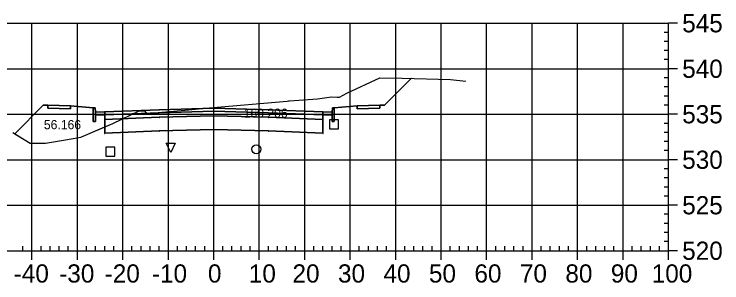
# Model space of a CAD drawing. Extents: x 704834 to 709892, y 372981 to 377533.
# Drawn here: x 705543 to 705698.6, y 373825.8 to 373884.8 of the extents above; entities that cross this region are included whole.
import ezdxf

# ---------------------------------------------------------------- set-up
doc = ezdxf.new("R2010")
doc.units = 0
for name, color, linetype in [('1', 7, 'Continuous'), ('10', 7, 'Continuous'), ('13', 7, 'Continuous'), ('14', 7, 'Continuous'), ('4', 7, 'Continuous'), ('57', 7, 'Continuous'), ('59', 7, 'Continuous'), ('Default_Xsect', 7, 'Continuous'), ('Existing', 7, 'Continuous')]:
    doc.layers.add(name, color=color, linetype=linetype)

msp = doc.modelspace()

# ---------------------------------------------------------------- linework, layer by layer
for points in [[(705624.37, 373864.81), (705630.25, 373870.68)], [(705549.37, 373864.81), (705543.1, 373858.54)], [(705550.37, 373864.85), (705549.37, 373864.81)], [(705560.37, 373864.25), (705555.37, 373864.65)], [(705613.37, 373864.25), (705618.37, 373864.65)], [(705623.37, 373864.85), (705624.37, 373864.81)]]:
    msp.add_lwpolyline(points)
for points in [[(705555.37, 373864.65), (705550.37, 373864.85), (705550.37, 373864.18), (705555.37, 373863.98)], [(705560.87, 373863.25), (705560.79, 373864.25), (705560.37, 373864.25), (705560.37, 373861.25), (705560.87, 373861.25)], [(705586.87, 373863.5), (705598.87, 373863.14), (705610.87, 373862.66), (705610.87, 373863.33), (705598.87, 373863.81), (705586.87, 373864.17), (705574.87, 373863.81), (705562.87, 373863.33), (705562.87, 373862.66), (705574.87, 373863.14)], [(705586.87, 373862.5), (705598.87, 373862.14), (705610.87, 373861.66), (705610.87, 373862.66), (705598.87, 373863.14), (705586.87, 373863.5), (705574.87, 373863.14), (705562.87, 373862.66), (705562.87, 373861.66), (705574.87, 373862.14)], [(705586.82, 373863.45), (705586.92, 373863.45), (705586.92, 373863.55), (705586.82, 373863.55)], [(705612.87, 373861.25), (705613.37, 373861.25), (705613.37, 373864.25), (705612.96, 373864.25), (705612.87, 373863.25)], [(705618.37, 373863.98), (705623.37, 373864.18), (705623.37, 373864.85), (705618.37, 373864.65)], [(705562.87, 373863.33), (705560.87, 373863.25), (705560.87, 373862.58), (705562.87, 373862.66)], [(705586.87, 373859.5), (705598.87, 373859.14), (705610.87, 373858.66), (705610.87, 373861.66), (705598.87, 373862.14), (705586.87, 373862.5), (705574.87, 373862.14), (705562.87, 373861.66), (705562.87, 373858.66), (705574.87, 373859.14)], [(705574.82, 373862.09), (705574.92, 373862.09), (705574.92, 373862.19), (705574.82, 373862.19)], [(705586.82, 373862.45), (705586.92, 373862.45), (705586.92, 373862.55), (705586.82, 373862.55)], [(705598.82, 373862.09), (705598.92, 373862.09), (705598.92, 373862.19), (705598.82, 373862.19)], [(705610.87, 373862.66), (705612.87, 373862.58), (705612.87, 373863.25), (705610.87, 373863.33)], [(705562.82, 373861.61), (705562.92, 373861.61), (705562.92, 373861.71), (705562.82, 373861.71)], [(705610.82, 373861.61), (705610.92, 373861.61), (705610.92, 373861.71), (705610.82, 373861.71)], [(705574.82, 373859.09), (705574.92, 373859.09), (705574.92, 373859.19), (705574.82, 373859.19)], [(705586.82, 373859.45), (705586.92, 373859.45), (705586.92, 373859.55), (705586.82, 373859.55)], [(705598.82, 373859.09), (705598.92, 373859.09), (705598.92, 373859.19), (705598.82, 373859.19)], [(705562.82, 373858.61), (705562.92, 373858.61), (705562.92, 373858.71), (705562.82, 373858.71)], [(705610.82, 373858.61), (705610.92, 373858.61), (705610.92, 373858.71), (705610.82, 373858.71)]]:
    msp.add_lwpolyline(points, close=True)
at = {"layer": '1'}
for points in [[(705562.87, 373860.06), (705564.64, 373860.82), (705570.46, 373863.6), (705571.62, 373863.57), (705571.93, 373863.22), (705572.08, 373862.98), (705580.47, 373863.69), (705585.91, 373864.24), (705602.98, 373865.71), (705603.32, 373865.74), (705603.48, 373865.76), (705609.7, 373866.21), (705612.74, 373866.61), (705613.99, 373866.57), (705614.5, 373866.6), (705616.1, 373867.46), (705623.36, 373870.82), (705628.27, 373870.74), (705630.25, 373870.68), (705624.37, 373864.81), (705623.37, 373864.85), (705623.37, 373864.18), (705618.37, 373863.98), (705618.37, 373864.65), (705613.37, 373864.25), (705613.37, 373861.25), (705612.87, 373861.25), (705612.87, 373862.58), (705610.87, 373862.66), (705610.87, 373861.66), (705610.87, 373858.66), (705598.87, 373859.14), (705586.87, 373859.5), (705574.87, 373859.14), (705562.87, 373858.66)], [(705543.1, 373858.54), (705546.51, 373856.46), (705549.89, 373856.43), (705553.82, 373857.14), (705557.64, 373857.79), (705562.87, 373860.06), (705562.87, 373861.66), (705562.87, 373862.66), (705560.87, 373862.58), (705560.87, 373861.25), (705560.37, 373861.25), (705560.37, 373864.25), (705555.37, 373864.65), (705555.37, 373863.98), (705550.37, 373864.18), (705550.37, 373864.85), (705549.37, 373864.81)], [(705577.4, 373854.43), (705576.4, 373856.43), (705578.4, 373856.43)]]:
    msp.add_lwpolyline(points, close=True, dxfattribs=at)
at = {"layer": '10'}
msp.add_lwpolyline([(705563.14, 373853.6), (705565.14, 373853.6), (705565.14, 373855.6), (705563.14, 373855.6)], close=True, dxfattribs=at)
at = {"layer": '13'}
msp.add_circle((705596.2, 373855.13), 1, dxfattribs=at)
at = {"layer": '14'}
for points in [[(705630.25, 373870.68), (705630.25, 373870.73), (705630.25, 373870.68), (705630.2, 373870.68), (705630.25, 373870.68), (705630.25, 373870.63), (705630.25, 373870.68), (705630.3, 373870.68)], [(705574.87, 373863.81), (705574.87, 373863.86), (705574.87, 373863.81), (705574.82, 373863.81), (705574.87, 373863.81), (705574.87, 373863.76), (705574.87, 373863.81), (705574.92, 373863.81)], [(705586.87, 373864.17), (705586.87, 373864.22), (705586.87, 373864.17), (705586.82, 373864.17), (705586.87, 373864.17), (705586.87, 373864.12), (705586.87, 373864.17), (705586.92, 373864.17)], [(705598.87, 373863.81), (705598.87, 373863.86), (705598.87, 373863.81), (705598.82, 373863.81), (705598.87, 373863.81), (705598.87, 373863.76), (705598.87, 373863.81), (705598.92, 373863.81)], [(705562.87, 373863.33), (705562.87, 373863.38), (705562.87, 373863.33), (705562.82, 373863.33), (705562.87, 373863.33), (705562.87, 373863.28), (705562.87, 373863.33), (705562.92, 373863.33)], [(705610.87, 373863.33), (705610.87, 373863.38), (705610.87, 373863.33), (705610.82, 373863.33), (705610.87, 373863.33), (705610.87, 373863.28), (705610.87, 373863.33), (705610.92, 373863.33)], [(705543.1, 373858.54), (705543.1, 373858.59), (705543.1, 373858.54), (705543.05, 373858.54), (705543.1, 373858.54), (705543.1, 373858.49), (705543.1, 373858.54), (705543.15, 373858.54)]]:
    msp.add_lwpolyline(points, dxfattribs=at)
at = {"layer": '4'}
msp.add_lwpolyline([(705612.32, 373859.59), (705614.32, 373859.59), (705614.32, 373861.59), (705612.32, 373861.59)], close=True, dxfattribs=at)
at = {"layer": '57'}
for p, q in [((705486.87, 373882.82), (705686.87, 373882.82)), ((705546.87, 373832.82), (705546.87, 373882.82)), ((705556.87, 373832.82), (705556.87, 373882.82)), ((705566.87, 373832.82), (705566.87, 373882.82)), ((705576.87, 373832.82), (705576.87, 373882.82)), ((705586.87, 373832.82), (705586.87, 373882.82)), ((705596.87, 373832.82), (705596.87, 373882.82)), ((705606.87, 373832.82), (705606.87, 373882.82)), ((705616.87, 373832.82), (705616.87, 373882.82)), ((705626.87, 373832.82), (705626.87, 373882.82)), ((705636.87, 373832.82), (705636.87, 373882.82)), ((705646.87, 373832.82), (705646.87, 373882.82)), ((705656.87, 373832.82), (705656.87, 373882.82)), ((705666.87, 373832.82), (705666.87, 373882.82)), ((705676.87, 373832.82), (705676.87, 373882.82)), ((705686.87, 373832.82), (705686.87, 373882.82)), ((705686.87, 373832.82), (705686.87, 373882.82)), ((705688.87, 373882.82), (705686.87, 373882.82)), ((705686.87, 373880.82), (705685.87, 373880.82)), ((705686.87, 373878.82), (705685.87, 373878.82)), ((705686.87, 373876.82), (705685.87, 373876.82)), ((705686.87, 373874.82), (705685.87, 373874.82)), ((705486.87, 373872.82), (705686.87, 373872.82)), ((705688.87, 373872.82), (705686.87, 373872.82)), ((705686.87, 373870.82), (705685.87, 373870.82)), ((705686.87, 373868.82), (705685.87, 373868.82)), ((705686.87, 373866.82), (705685.87, 373866.82)), ((705686.87, 373864.82), (705685.87, 373864.82)), ((705486.87, 373862.82), (705686.87, 373862.82)), ((705688.87, 373862.82), (705686.87, 373862.82)), ((705686.87, 373860.82), (705685.87, 373860.82)), ((705686.87, 373858.82), (705685.87, 373858.82)), ((705686.87, 373856.82), (705685.87, 373856.82)), ((705686.87, 373854.82), (705685.87, 373854.82)), ((705486.87, 373852.82), (705686.87, 373852.82)), ((705688.87, 373852.82), (705686.87, 373852.82)), ((705686.87, 373850.82), (705685.87, 373850.82)), ((705686.87, 373848.82), (705685.87, 373848.82)), ((705686.87, 373846.82), (705685.87, 373846.82)), ((705686.87, 373844.82), (705685.87, 373844.82)), ((705486.87, 373842.82), (705686.87, 373842.82)), ((705688.87, 373842.82), (705686.87, 373842.82)), ((705686.87, 373840.82), (705685.87, 373840.82)), ((705686.87, 373838.82), (705685.87, 373838.82)), ((705686.87, 373836.82), (705685.87, 373836.82)), ((705686.87, 373834.82), (705685.87, 373834.82)), ((705486.87, 373832.82), (705686.87, 373832.82)), ((705486.87, 373832.82), (705686.87, 373832.82)), ((705544.87, 373832.82), (705544.87, 373833.82)), ((705546.87, 373830.82), (705546.87, 373832.82)), ((705548.87, 373832.82), (705548.87, 373833.82)), ((705550.87, 373832.82), (705550.87, 373833.82)), ((705552.87, 373832.82), (705552.87, 373833.82)), ((705554.87, 373832.82), (705554.87, 373833.82)), ((705556.87, 373830.82), (705556.87, 373832.82)), ((705558.87, 373832.82), (705558.87, 373833.82)), ((705560.87, 373832.82), (705560.87, 373833.82)), ((705562.87, 373832.82), (705562.87, 373833.82)), ((705564.87, 373832.82), (705564.87, 373833.82)), ((705566.87, 373830.82), (705566.87, 373832.82)), ((705568.87, 373832.82), (705568.87, 373833.82)), ((705570.87, 373832.82), (705570.87, 373833.82)), ((705572.87, 373832.82), (705572.87, 373833.82)), ((705574.87, 373832.82), (705574.87, 373833.82)), ((705576.87, 373830.82), (705576.87, 373832.82)), ((705578.87, 373832.82), (705578.87, 373833.82)), ((705580.87, 373832.82), (705580.87, 373833.82)), ((705582.87, 373832.82), (705582.87, 373833.82)), ((705584.87, 373832.82), (705584.87, 373833.82)), ((705586.87, 373830.82), (705586.87, 373832.82)), ((705588.87, 373832.82), (705588.87, 373833.82)), ((705590.87, 373832.82), (705590.87, 373833.82)), ((705592.87, 373832.82), (705592.87, 373833.82)), ((705594.87, 373832.82), (705594.87, 373833.82)), ((705596.87, 373830.82), (705596.87, 373832.82)), ((705598.87, 373832.82), (705598.87, 373833.82)), ((705600.87, 373832.82), (705600.87, 373833.82)), ((705602.87, 373832.82), (705602.87, 373833.82)), ((705604.87, 373832.82), (705604.87, 373833.82)), ((705606.87, 373830.82), (705606.87, 373832.82)), ((705608.87, 373832.82), (705608.87, 373833.82)), ((705610.87, 373832.82), (705610.87, 373833.82)), ((705612.87, 373832.82), (705612.87, 373833.82)), ((705614.87, 373832.82), (705614.87, 373833.82)), ((705616.87, 373830.82), (705616.87, 373832.82)), ((705618.87, 373832.82), (705618.87, 373833.82)), ((705620.87, 373832.82), (705620.87, 373833.82)), ((705622.87, 373832.82), (705622.87, 373833.82)), ((705624.87, 373832.82), (705624.87, 373833.82)), ((705626.87, 373830.82), (705626.87, 373832.82)), ((705628.87, 373832.82), (705628.87, 373833.82)), ((705630.87, 373832.82), (705630.87, 373833.82)), ((705632.87, 373832.82), (705632.87, 373833.82)), ((705634.87, 373832.82), (705634.87, 373833.82)), ((705636.87, 373830.82), (705636.87, 373832.82)), ((705638.87, 373832.82), (705638.87, 373833.82)), ((705640.87, 373832.82), (705640.87, 373833.82)), ((705642.87, 373832.82), (705642.87, 373833.82)), ((705644.87, 373832.82), (705644.87, 373833.82)), ((705646.87, 373830.82), (705646.87, 373832.82)), ((705648.87, 373832.82), (705648.87, 373833.82)), ((705650.87, 373832.82), (705650.87, 373833.82)), ((705652.87, 373832.82), (705652.87, 373833.82)), ((705654.87, 373832.82), (705654.87, 373833.82)), ((705656.87, 373830.82), (705656.87, 373832.82)), ((705658.87, 373832.82), (705658.87, 373833.82)), ((705660.87, 373832.82), (705660.87, 373833.82)), ((705662.87, 373832.82), (705662.87, 373833.82)), ((705664.87, 373832.82), (705664.87, 373833.82)), ((705666.87, 373830.82), (705666.87, 373832.82)), ((705668.87, 373832.82), (705668.87, 373833.82)), ((705670.87, 373832.82), (705670.87, 373833.82)), ((705672.87, 373832.82), (705672.87, 373833.82)), ((705674.87, 373832.82), (705674.87, 373833.82)), ((705676.87, 373830.82), (705676.87, 373832.82)), ((705678.87, 373832.82), (705678.87, 373833.82)), ((705680.87, 373832.82), (705680.87, 373833.82)), ((705682.87, 373832.82), (705682.87, 373833.82)), ((705684.87, 373832.82), (705684.87, 373833.82)), ((705686.87, 373830.82), (705686.87, 373832.82)), ((705688.87, 373832.82), (705686.87, 373832.82))]:
    msp.add_line(p, q, dxfattribs=at)
at = {"layer": 'Default_Xsect'}
msp.add_lwpolyline([(705543.1, 373858.54), (705549.37, 373864.81), (705550.37, 373864.85), (705555.37, 373864.65), (705560.37, 373864.25), (705560.79, 373864.25), (705560.87, 373863.25), (705562.87, 373863.33), (705574.87, 373863.81), (705586.87, 373864.17), (705598.87, 373863.81), (705610.87, 373863.33), (705612.87, 373863.25), (705612.96, 373864.25), (705613.37, 373864.25), (705618.37, 373864.65), (705623.37, 373864.85), (705624.37, 373864.81), (705630.25, 373870.68)], dxfattribs=at)
at = {"layer": 'Existing'}
msp.add_lwpolyline([(705542.67, 373858.81), (705546.51, 373856.46), (705549.89, 373856.43), (705553.82, 373857.14), (705557.64, 373857.79), (705564.64, 373860.82), (705570.46, 373863.6), (705571.62, 373863.57), (705571.93, 373863.22), (705572.08, 373862.98), (705580.47, 373863.69), (705585.91, 373864.24), (705602.98, 373865.71), (705603.32, 373865.74), (705603.48, 373865.76), (705609.7, 373866.21), (705612.74, 373866.61), (705613.99, 373866.57), (705614.5, 373866.6), (705616.1, 373867.46), (705623.36, 373870.82), (705628.27, 373870.74), (705638.91, 373870.42), (705642.28, 373870.1)], dxfattribs=at)

# ---------------------------------------------------------------- texts
at = {"layer": '14'}
for p in [(705550.34, 373864.8), (705550.34, 373864.13), (705555.34, 373863.93), (705618.34, 373863.93), (705623.34, 373864.8), (705623.34, 373864.13)]:
    msp.add_text('+', height=0.1, dxfattribs=at).set_placement(p)
at = {"layer": '57'}
for s, p in [('545', (705689.87, 373880.82)), ('540', (705689.87, 373870.82)), ('535', (705689.87, 373860.82)), ('530', (705689.87, 373850.82)), ('525', (705689.87, 373840.82)), ('520', (705689.87, 373830.82)), ('-40', (705542.87, 373825.82)), ('-30', (705552.87, 373825.82)), ('-20', (705562.87, 373825.82)), ('-10', (705573.26, 373825.82)), ('0', (705585.58, 373825.82)), ('10', (705594.57, 373825.82)), ('20', (705604.18, 373825.82)), ('30', (705614.18, 373825.82)), ('40', (705624.18, 373825.82)), ('50', (705634.18, 373825.82)), ('60', (705644.18, 373825.82)), ('70', (705654.18, 373825.82)), ('80', (705664.18, 373825.82)), ('90', (705674.18, 373825.82)), ('100', (705683.17, 373825.82))]:
    msp.add_text(s, height=4, dxfattribs=at).set_placement(p)
at = {"layer": '59'}
for s, p in [('160.206', (705593.44, 373862.06)), ('56.166', (705549.5, 373859.53))]:
    msp.add_text(s, height=2, dxfattribs=at).set_placement(p)

doc.saveas('drawing.dxf')
